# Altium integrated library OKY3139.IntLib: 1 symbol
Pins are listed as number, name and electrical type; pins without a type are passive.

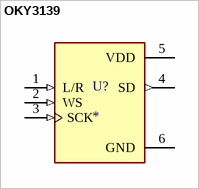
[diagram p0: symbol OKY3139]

## OKY3139
designator U?
Module: audio; microphone; I2S; IC: INMP441; SNR: 61dB; 60HzÃ·15kHz; MF: okystar; MP: OKY3139
footprint MODULE_OKY3139
pins: 1 L/R (in), 2 WS (in), 3 SCK (in), 4 SD (out), 5 VDD (power), 6 GND (power)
